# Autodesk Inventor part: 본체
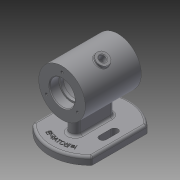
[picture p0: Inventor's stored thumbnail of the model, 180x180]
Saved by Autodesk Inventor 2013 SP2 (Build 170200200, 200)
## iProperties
Created: 2022-02
Part Number: 본체
Material: Generic
Document SubType Name: Modeling
Designer: a
Density: 1 g/cm^3
Author: a
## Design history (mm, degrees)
sketch "스케치1"
  geometry: C1 r 30 at (0, 0); 1 further point
  constraints: 1 centre point, 1 coincident
  dimensions: "d0" = 60 diameter of C1
extrude "돌출1" new body sketch "스케치1" stored distance "d1" = 72; taper "d2" = 0 deg
node "작업 평면1"
sketch "스케치2"
  geometry: L1 (38, 35.496)-(38, -35.496); L2 (-38, 35.496)-(-38, -35.496); A1 r 52 centre (0, 0) between (-38, -35.496) and (38, -35.496); A2 r 52 centre (0, 0) between (38, 35.496) and (-38, 35.496); 1 further point
  constraints: 4 end point, 4 point on circle, 2 centre point, 2 vertical, 1 coincident
  dimensions: "d5" = 76 distance between parallel lines of L2 L1; "d6" = 38 distance from line of point (0, 0) L1; "d7" = 52 radius of A1; "d8" = 52 radius of A2
extrude "돌출2" join sketch "스케치2" distance "d9" = 10; taper "d10" = 0 deg
sketch "스케치3"
  geometry: L1 (38, -35.496)-(38, 35.496) reference; L2 (-7, -19)-(-7, 19); L3 (7, -19)-(7, 19); A1 r 52 centre (0, 0) between (-38, -35.496) and (38, -35.496) reference; A2 r 7 centre (0, -19) between (-7, -19) and (7, -19); A3 r 7 centre (0, 19) between (7, 19) and (-7, 19)
  constraints: 4 end point, 4 point on circle, 3 tangent, 2 centre point, 2 parallel, 1 vertical alignment
  dimensions: "d11" = 14 diameter of A2; "d12" = 14 diameter of A3; "d13" = 38 distance of A3.centre A2.centre; "d14" = 19 distance of A1.centre A3.centre
extrude "돌출3" join sketch "스케치3" stored distance "d15" = 10; taper "d16" = 0 deg
sketch "스케치4"
  geometry: L1 (0, 36)-(0, -36); L2 (30, 36)-(-30, 36) reference; L3 (-30, -36)-(30, -36) reference; L4 (0, 36)-(16, 36); L5 (16, 36)-(16, 24); L6 (16, 24)-(14, 24); L7 (14, 24)-(14, 20); L8 (14, 20)-(25, 20); L9 (25, 20)-(25, -20); L10 (25, -20)-(14, -20); L11 (14, -20)-(14, -24); L12 (14, -24)-(16, -24); L13 (16, -24)-(16, -36); L14 (0, -36)-(16, -36); 2 further points
  constraints: 24 end point, 6 parallel, 4 perpendicular, 3 midpoint, 2 point on line, 1 coincident, 1 vertical
  dimensions: "d17" = 12 distance between parallel lines of L6 L4; "d19" = 40 distance between parallel lines of L10 L8; "d20" = 12 distance between parallel lines of L3 L12; "d21" = 32 diameter of L5 L1; "d22" = 28 diameter of L7 L1; "d23" = 50 diameter of L9 L1; "d24" = 32 diameter of L13 L1; "d25" = 28 diameter of L11 L1; "d26" = 4 distance between parallel lines of L12 L10
revolve "회전1" sketch "스케치4" stored, may be unused: angle "d27" = 90 deg
fillet "모깎기1" dims "d28" = 0.3
sketch "스케치5"
  geometry: L1 (0, 0)-(16.5, 28.579); L2 (0, 0)-(0, 17.884)
  constraints: 4 end point, 1 vertical
  dimensions: "d29" = 33 distance of L1.start L1.end; "d31" = 30 deg angle of L1 L2
node "작업 평면2"
sketch "스케치6"
  geometry: C1 r 8 at (0, 0); 1 further point
  constraints: 1 centre point, 1 coincident
  dimensions: "d32" = 16 diameter of C1
extrude "돌출4" join sketch "스케치6" distance "d33" = 5.08966; taper "d34" = 0 deg
sketch "스케치7"
  geometry: C1 r 8 at (0, 0) reference; C2 r 4 at (0, 0)
  constraints: 1 centre point, 1 coincident
  dimensions: "d35" = 8 diameter of C2
extrude "돌출5" cut sketch "스케치7" distance "d36" = 25.58966; taper "d37" = 0 deg
fillet "모깎기2" dims "d38" = 1
sketch "스케치8"
  geometry: L1 (38, -35.496)-(38, 35.496) reference; L2 (-28.5, -7.5)-(-28.5, 7.5); L3 (-19.5, -7.5)-(-19.5, 7.5); A1 r 7 centre (0, 19) between (7, 19) and (-7, 19) reference; A2 r 52 centre (0, 0) between (-38, -35.496) and (38, -35.496) reference; A3 r 4.5 centre (-24, -7.5) between (-28.5, -7.5) and (-19.5, -7.5); A4 r 4.5 centre (-24, 7.5) between (-19.5, 7.5) and (-28.5, 7.5)
  constraints: 4 end point, 4 point on circle, 3 tangent, 2 centre point, 2 parallel
  dimensions: "d39" = 9 diameter of A3; "d40" = 9 diameter of A4; "d41" = 24 horizontal distance of A1.centre A4.centre; "d42" = 15 distance of A4.centre A3.centre; "d43" = 7.5 vertical distance of A2.centre A4.centre
extrude "돌출6" cut sketch "스케치8" stored distance "d44" = 25.58966; taper "d45" = 0 deg
sketch "스케치9"
  geometry: C1 r 42.5 at (0, 0); A1 r 52 centre (0, 0) between (38, 35.496) and (-38, 35.496) reference
  constraints: 1 centre point, 1 coincident, 1 other
  dimensions: "d46" = 85 diameter of C1
feature "엠보싱1" sketch "스케치9" dims "d11" = 14, "d12" = 14, "d13" = 38, "d14" = 19, "d47" = 0.5, "d48" = 0
fillet "모깎기3" dims "d49" = 3
fillet "모깎기4" dims "d50" = 3
fillet "모깎기5" dims "d51" = 3
fillet "모깎기6" dims "d52" = 3
sketch "스케치10"
  geometry: C1 r 16 at (0, 0) reference; 1 further point
  constraints: 1 vertical alignment
  dimensions: "d53" = 23 distance of C1.centre point (0, 23)
hole "구멍1" sketch "스케치10" at (0, 23) diameter "d54" = 3.242; stored, may be unused: countersink angle "d58" = 90 deg, drill point angle "d60" = 118 deg; dims "d55" = 8, "d56" = 4, "d57" = 2, "d59" = 10
chamfer "모따기1" distance "d64" = 1; stored, may be unused: second distance "d65" = 2, angle "d66" = 45 deg
fillet "모깎기7" dims "d67" = 3
fillet "모깎기8" dims "d68" = 1
node "솔리드1"
mirror "대칭1"
pattern_circular "원형 패턴1" dims angle "d62" = 360 deg
mirror "대칭2"
other parameters: "d3" = -62, "d4" = 104
